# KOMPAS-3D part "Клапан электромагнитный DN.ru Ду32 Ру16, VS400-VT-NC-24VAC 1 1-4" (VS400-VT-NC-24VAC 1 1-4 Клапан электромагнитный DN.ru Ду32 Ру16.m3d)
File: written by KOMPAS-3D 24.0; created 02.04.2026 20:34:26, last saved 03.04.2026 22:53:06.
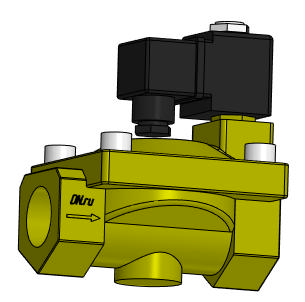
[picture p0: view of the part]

Document properties: Автор: artio; Полное имя файла: C:\Users\artio\OneDrive\Рабочий стол\Клапан электромагнитный DN.ru\VS400-VT-NC\VS400-VT-NC-24VAC 1 1-4 Клапан электромагнитный DN.ru Ду32 Ру16.m3d

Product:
- Body: Тело 1  | qty 1
    Масса: 4.144257
- Part/product: Клапан электромагнитный DN.ru Ду32 Ру16  | designation VS400-VT-NC-24VAC 1 1-4
    Масса: 2.569
    Раздел спецификации: Прочие изделия
    Примечание: D130-05500
    additional columns: ef56311e-7521-43dc-8291-0e6108b3d81d; VS400-ET-NC-220VAC 1 1-4; artio; c; Шероховатость не задана; Да

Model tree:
1. Операция без истории:1

Expressions: VS400-VT-NC-24VAC 1 1-4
